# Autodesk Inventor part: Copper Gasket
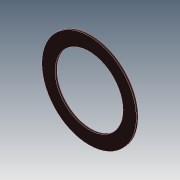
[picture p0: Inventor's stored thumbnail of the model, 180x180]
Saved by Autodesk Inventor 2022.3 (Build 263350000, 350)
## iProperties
Created: 2023-08
Part Number: Copper Gasket
Material: Generic
Document SubType Name: Modeling
Designer: irinventor.com
Density: 1 g/cm^3
Appearance: Default(2)
Author: irinventor.com
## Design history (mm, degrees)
sketch "Sketch1"
  geometry: C1 r 25 at (0, 0); C2 r 18 at (0, 0); 1 further point
  constraints: 2 centre point, 2 coincident
  dimensions: "d0" = 50 diameter of C1; "d1" = 7 radial gap between concentric circles of C1 C2
extrude "Extrusion1" new body sketch "Sketch1" distance "d2" = 1; taper "d3" = 0 deg
body "Solid1"
